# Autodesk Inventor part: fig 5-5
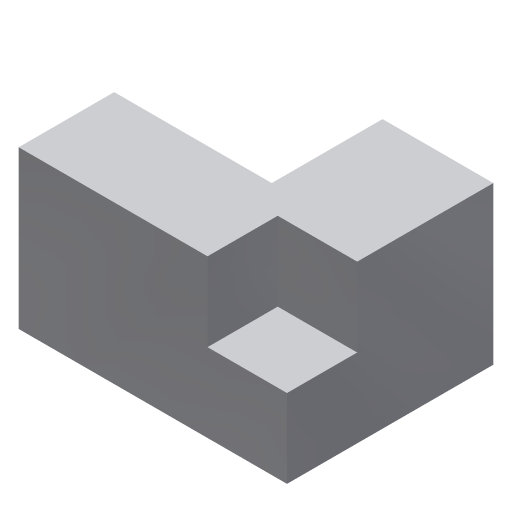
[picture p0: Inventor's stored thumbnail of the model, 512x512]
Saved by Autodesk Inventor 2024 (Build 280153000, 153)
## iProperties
Created: 2010-02
Part Number: fig 5-5
Document SubType Name: Modeling
Designer: CADSoft
Density: 1 g/cm^3
Material: Generic
Appearance: Default
Author: CADSoft
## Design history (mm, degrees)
sketch "Sketch1"
  geometry: L1 (0, 26.227)-(0, 12.145); L2 (0, 12.145)-(-20.026, 12.145); L3 (-20.026, 12.145)-(-20.026, 0); L4 (-20.026, 0)-(14.083, 0); L5 (14.083, 0)-(14.083, 26.227); L6 (14.083, 26.227)-(0, 26.227); 1 further point
  constraints: 12 end point
extrude "Extrusion1" new body sketch "Sketch1" distance "d0" = 20; taper "d1" = 0 deg
sketch "Sketch2"
  geometry: L1 (14.083, 0)-(3.983, 0); L2 (3.983, 0)-(3.983, 8.922); L3 (3.983, 8.922)-(14.083, 8.922); L4 (14.083, 8.922)-(14.083, 0); 1 further point
  constraints: 8 end point
extrude "Extrusion2" cut sketch "Sketch2" distance "d2" = 10; taper "d3" = 0 deg
body "Solid1"
